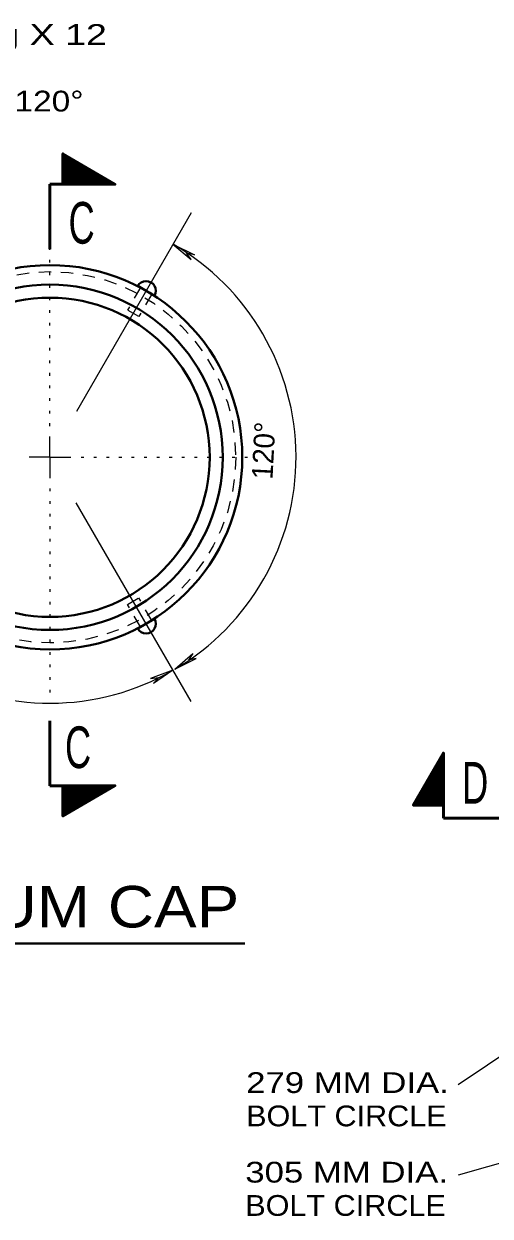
# Model space of a CAD drawing. Extents: x 312583 to 312854, y 144418 to 144597.
# Drawn here: x 312757.76 to 312774.81, y 144501.21 to 144544.83 of the extents above; entities that cross this region are included whole.
import ezdxf
from ezdxf.enums import TextEntityAlignment as Align

# ---------------------------------------------------------------- set-up
doc = ezdxf.new("R2010")
doc.units = 0
doc.header["$LTSCALE"] = 0.3
doc.linetypes.add('DOTTED', pattern=[1.5, 0.3, -1.2])
doc.linetypes.add('SHORT_DASHED', pattern=[2.7, 1.5, -1.2])
doc.layers.add('1', color=7, linetype='Continuous', lineweight=35)

msp = doc.modelspace()

# ---------------------------------------------------------------- linework, layer by layer
at = {"layer": '1'}
for p, q in [((312759.1879, 144540.0442), (312759.2032, 144540.0594)), ((312759.1879, 144539.9984), (312759.226, 144540.0442)), ((312759.1879, 144539.9374), (312759.2413, 144540.0289)), ((312759.1879, 144539.8917), (312759.2642, 144540.0137)), ((312759.1879, 144539.8459), (312759.287, 144540.0137)), ((312759.1879, 144539.8002), (312759.3023, 144539.9984)), ((312759.1879, 144539.7544), (312759.3252, 144539.9832)), ((312759.1879, 144539.7087), (312759.348, 144539.9679)), ((312759.1879, 144539.6629), (312759.3633, 144539.9679)), ((312759.1879, 144539.6172), (312759.3938, 144539.9527)), ((312759.1879, 144539.5562), (312759.409, 144539.9374)), ((312759.1879, 144539.5104), (312759.4319, 144539.9222)), ((312759.1879, 144539.4647), (312759.4548, 144539.9222)), ((312759.1879, 144539.4189), (312759.47, 144539.9069)), ((312759.1879, 144539.3732), (312759.4929, 144539.8917)), ((312759.1879, 144539.3274), (312759.5082, 144539.8764)), ((312759.1879, 144539.2664), (312759.531, 144539.8612)), ((312759.1879, 144539.2207), (312759.5539, 144539.8612)), ((312759.1879, 144539.1749), (312759.5692, 144539.8459)), ((312759.1879, 144539.1292), (312759.592, 144539.8307)), ((312759.1879, 144539.0834), (312759.6149, 144539.8154)), ((312759.1879, 144539.0377), (312759.6302, 144539.8002)), ((312759.1879, 144538.9919), (312759.6606, 144539.8002)), ((312759.2032, 144538.9614), (312759.6759, 144539.7849)), ((312759.2336, 144538.9614), (312759.6988, 144539.7697)), ((312759.2642, 144538.9614), (312759.7216, 144539.7544)), ((312759.287, 144538.9614), (312759.7369, 144539.7544)), ((312759.3175, 144538.9614), (312759.7598, 144539.7392)), ((312759.3404, 144538.9767), (312759.7826, 144539.7239)), ((312759.3709, 144538.9767), (312759.7979, 144539.7087)), ((312759.3938, 144538.9614), (312759.8208, 144539.7087)), ((312759.4243, 144538.9614), (312759.8436, 144539.6934)), ((312759.4548, 144538.9614), (312759.8589, 144539.6782)), ((312759.4776, 144538.9614), (312759.8818, 144539.6629)), ((312759.5082, 144538.9614), (312759.9046, 144539.6477)), ((312759.5386, 144538.9614), (312759.9275, 144539.6324)), ((312759.5615, 144538.9614), (312759.9428, 144539.6324)), ((312759.592, 144538.9767), (312759.9656, 144539.6172)), ((312759.6225, 144538.9614), (312759.9885, 144539.6019)), ((312759.6454, 144538.9614), (312760.0038, 144539.5867)), ((312759.6683, 144538.9614), (312760.0266, 144539.5867)), ((312759.6988, 144538.9614), (312760.0495, 144539.5714)), ((312759.7293, 144538.9614), (312760.0648, 144539.5562)), ((312759.7598, 144538.9614), (312760.0876, 144539.5409)), ((312759.7826, 144538.9614), (312760.1105, 144539.5409)), ((312759.8132, 144538.9614), (312760.1258, 144539.5257)), ((312759.836, 144538.9767), (312760.1563, 144539.5104)), ((312759.8665, 144538.9614), (312760.1715, 144539.4952)), ((312759.8894, 144538.9614), (312760.1944, 144539.4799)), ((312759.9199, 144538.9614), (312760.2173, 144539.4799)), ((312759.9504, 144538.9614), (312760.2325, 144539.4647)), ((312759.9733, 144538.9614), (312760.2554, 144539.4494)), ((312760.0038, 144538.9614), (312760.2783, 144539.4342)), ((312760.0343, 144538.9614), (312760.2935, 144539.4342)), ((312760.0572, 144538.9614), (312760.3164, 144539.4189)), ((312760.0876, 144538.9614), (312760.3393, 144539.4037)), ((312760.1182, 144538.9614), (312760.3545, 144539.3884)), ((312760.141, 144538.9614), (312760.3774, 144539.3884)), ((312760.1639, 144538.9614), (312760.4003, 144539.3732)), ((312760.1944, 144538.9614), (312760.4232, 144539.3579)), ((312760.2249, 144538.9614), (312760.4384, 144539.3427)), ((312760.2554, 144538.9614), (312760.4613, 144539.3274)), ((312760.2783, 144538.9614), (312760.4842, 144539.3274)), ((312760.3088, 144538.9614), (312760.4994, 144539.3122)), ((312760.3316, 144538.9614), (312760.5223, 144539.2969)), ((312760.3622, 144538.9614), (312760.5452, 144539.2817)), ((312760.385, 144538.9614), (312760.5604, 144539.2664)), ((312760.4155, 144538.9614), (312760.5833, 144539.2664)), ((312760.446, 144538.9614), (312760.6062, 144539.2512)), ((312760.4689, 144538.9614), (312760.6214, 144539.2359)), ((312760.4994, 144538.9614), (312760.6519, 144539.2207)), ((312760.5223, 144538.9614), (312760.6672, 144539.2207)), ((312760.5528, 144538.9614), (312760.69, 144539.2054)), ((312760.5833, 144538.9614), (312760.7129, 144539.1902)), ((312760.6062, 144538.9614), (312760.7282, 144539.1749)), ((312760.6366, 144538.9614), (312760.751, 144539.1749)), ((312760.6595, 144538.9614), (312760.7739, 144539.1597)), ((312760.69, 144538.9614), (312760.7892, 144539.1444)), ((312760.7205, 144538.9614), (312760.812, 144539.1292)), ((312760.751, 144538.9614), (312760.8349, 144539.1139)), ((312760.7739, 144538.9614), (312760.8502, 144539.0987)), ((312760.8044, 144538.9614), (312760.873, 144539.0987)), ((312760.8273, 144538.9614), (312760.8959, 144539.0834)), ((312760.8502, 144538.9614), (312760.9188, 144539.0682)), ((312760.8806, 144538.9614), (312760.934, 144539.0529)), ((312760.9112, 144538.9614), (312760.9569, 144539.0529)), ((312760.9416, 144538.9614), (312760.9798, 144539.0377)), ((312760.9645, 144538.9614), (312760.995, 144539.0224)), ((312760.995, 144538.9614), (312761.0179, 144539.0072)), ((312761.0179, 144538.9614), (312761.0408, 144539.0072)), ((312761.0484, 144538.9614), (312761.056, 144538.9919)), ((312761.0789, 144538.9614), (312761.0789, 144538.9767)), ((312773.105, 144517.8125), (312772.9525, 144517.8964)), ((312773.105, 144517.8354), (312772.9678, 144517.9116)), ((312773.105, 144517.8659), (312772.9754, 144517.9345)), ((312773.105, 144517.8888), (312772.9906, 144517.9574)), ((312773.105, 144517.9116), (312772.9982, 144517.9802)), ((312773.105, 144517.9421), (312773.0135, 144517.9955)), ((312773.105, 144517.9726), (312773.0211, 144518.0184)), ((312773.105, 144518.0031), (312773.0364, 144518.0412)), ((312773.105, 144518.026), (312773.044, 144518.0565)), ((312773.105, 144518.0565), (312773.0592, 144518.0794)), ((312773.105, 144518.0794), (312773.0669, 144518.1022)), ((312773.105, 144518.1099), (312773.0821, 144518.1175)), ((312773.105, 144518.1404), (312773.0898, 144518.1404)), ((312773.105, 144517.2254), (312772.7009, 144517.4618)), ((312773.105, 144517.2559), (312772.7085, 144517.4846)), ((312773.105, 144517.2864), (312772.7238, 144517.4999)), ((312773.105, 144517.3169), (312772.739, 144517.5228)), ((312773.105, 144517.3398), (312772.7466, 144517.5456)), ((312773.105, 144517.3702), (312772.7619, 144517.5609)), ((312773.105, 144517.3931), (312772.7771, 144517.5838)), ((312773.105, 144517.4236), (312772.7848, 144517.6066)), ((312773.105, 144517.4465), (312772.8, 144517.6219)), ((312773.105, 144517.477), (312772.8076, 144517.6448)), ((312773.105, 144517.5075), (312772.8229, 144517.6676)), ((312773.105, 144517.5304), (312772.8305, 144517.6829)), ((312773.105, 144517.5609), (312772.8458, 144517.7134)), ((312773.105, 144517.5838), (312772.8534, 144517.7286)), ((312773.105, 144517.6142), (312772.8686, 144517.7515)), ((312773.105, 144517.6448), (312772.8762, 144517.7744)), ((312773.105, 144517.6676), (312772.8915, 144517.7896)), ((312773.105, 144517.6981), (312772.8991, 144517.8125)), ((312773.105, 144517.721), (312772.9144, 144517.8354)), ((312773.105, 144517.7515), (312772.9296, 144517.8506)), ((312773.105, 144517.782), (312772.9372, 144517.8735)), ((312773.0974, 144516.6535), (312772.4569, 144517.0271)), ((312773.105, 144516.684), (312772.4645, 144517.05)), ((312773.105, 144516.7069), (312772.4798, 144517.0652)), ((312773.105, 144516.7298), (312772.4874, 144517.0881)), ((312773.105, 144516.7602), (312772.5026, 144517.111)), ((312773.105, 144516.7908), (312772.5102, 144517.1262)), ((312773.105, 144516.8212), (312772.5255, 144517.1491)), ((312773.105, 144516.8441), (312772.5331, 144517.172)), ((312773.105, 144516.8746), (312772.5484, 144517.1872)), ((312773.0974, 144516.8975), (312772.556, 144517.2178)), ((312773.105, 144516.928), (312772.5712, 144517.233)), ((312773.105, 144516.9509), (312772.5865, 144517.2559)), ((312773.105, 144516.9814), (312772.5941, 144517.2788)), ((312773.105, 144517.0119), (312772.6094, 144517.294)), ((312773.105, 144517.0348), (312772.617, 144517.3169)), ((312773.105, 144517.0652), (312772.6322, 144517.3398)), ((312773.105, 144517.0958), (312772.6399, 144517.355)), ((312773.105, 144517.1186), (312772.6551, 144517.3779)), ((312773.105, 144517.1491), (312772.6628, 144517.4008)), ((312773.105, 144517.1796), (312772.678, 144517.416)), ((312773.105, 144517.2025), (312772.6856, 144517.4389)), ((312759.1879, 144516.9328), (312759.6606, 144516.1246)), ((312759.1879, 144516.8794), (312759.6302, 144516.1169)), ((312759.1879, 144516.8413), (312759.6149, 144516.1017)), ((312759.1879, 144516.7879), (312759.592, 144516.094)), ((312759.1879, 144516.7422), (312759.5692, 144516.0788)), ((312759.1879, 144516.6964), (312759.5539, 144516.0636)), ((312759.1879, 144516.6507), (312759.531, 144516.0559)), ((312759.1879, 144516.5973), (312759.5082, 144516.0407)), ((312759.2032, 144516.9557), (312759.6759, 144516.1398)), ((312759.2336, 144516.9557), (312759.6988, 144516.1474)), ((312759.2642, 144516.9557), (312759.7216, 144516.1627)), ((312759.287, 144516.9557), (312759.7369, 144516.1703)), ((312759.3175, 144516.9557), (312759.7598, 144516.1856)), ((312759.3404, 144516.948), (312759.7826, 144516.1932)), ((312759.3709, 144516.948), (312759.7979, 144516.2084)), ((312759.3938, 144516.9557), (312759.8208, 144516.216)), ((312759.4243, 144516.9557), (312759.8436, 144516.2313)), ((312759.4548, 144516.9557), (312759.8589, 144516.2466)), ((312759.4776, 144516.9557), (312759.8818, 144516.2542)), ((312759.5082, 144516.9557), (312759.9046, 144516.2694)), ((312759.5386, 144516.9557), (312759.9275, 144516.2847)), ((312759.5615, 144516.9557), (312759.9428, 144516.2923)), ((312759.592, 144516.948), (312759.9656, 144516.3076)), ((312759.6225, 144516.9557), (312759.9885, 144516.3152)), ((312759.6454, 144516.9557), (312760.0038, 144516.3304)), ((312759.6683, 144516.9557), (312760.0266, 144516.338)), ((312759.6988, 144516.9557), (312760.0495, 144516.3533)), ((312759.7293, 144516.9557), (312760.0648, 144516.3609)), ((312759.7598, 144516.9557), (312760.0876, 144516.3762)), ((312759.7826, 144516.9557), (312760.1105, 144516.3838)), ((312759.8132, 144516.9557), (312760.1258, 144516.399)), ((312759.836, 144516.948), (312760.1563, 144516.4067)), ((312759.8665, 144516.9557), (312760.1715, 144516.4219)), ((312759.8894, 144516.9557), (312760.1944, 144516.4372)), ((312759.9199, 144516.9557), (312760.2173, 144516.4448)), ((312759.9504, 144516.9557), (312760.2325, 144516.46)), ((312759.9733, 144516.9557), (312760.2554, 144516.4677)), ((312760.0038, 144516.9557), (312760.2783, 144516.4829)), ((312760.0343, 144516.9557), (312760.2935, 144516.4906)), ((312760.0572, 144516.9557), (312760.3164, 144516.5058)), ((312760.0876, 144516.9557), (312760.3393, 144516.5134)), ((312760.1182, 144516.9557), (312760.3545, 144516.5287)), ((312760.141, 144516.9557), (312760.3774, 144516.5363)), ((312760.1639, 144516.9557), (312760.4003, 144516.5516)), ((312760.1944, 144516.9557), (312760.4232, 144516.5592)), ((312760.2249, 144516.9557), (312760.4384, 144516.5744)), ((312760.2554, 144516.9557), (312760.4613, 144516.5897)), ((312760.2783, 144516.9557), (312760.4842, 144516.5973)), ((312760.3088, 144516.9557), (312760.4994, 144516.6126)), ((312760.3316, 144516.9557), (312760.5223, 144516.6278)), ((312760.3622, 144516.9557), (312760.5452, 144516.6354)), ((312760.385, 144516.9557), (312760.5604, 144516.6507)), ((312760.4155, 144516.9557), (312760.5833, 144516.6583)), ((312760.446, 144516.9557), (312760.6062, 144516.6736)), ((312760.4689, 144516.9557), (312760.6214, 144516.6812)), ((312760.4994, 144516.9557), (312760.6519, 144516.6964)), ((312760.5223, 144516.9557), (312760.6672, 144516.704)), ((312760.5528, 144516.9557), (312760.69, 144516.7193)), ((312760.5833, 144516.9557), (312760.7129, 144516.7269)), ((312760.6062, 144516.9557), (312760.7282, 144516.7422)), ((312760.6366, 144516.9557), (312760.751, 144516.7498)), ((312760.6595, 144516.9557), (312760.7739, 144516.765)), ((312760.69, 144516.9557), (312760.7892, 144516.7803)), ((312760.7205, 144516.9557), (312760.812, 144516.7879)), ((312760.751, 144516.9557), (312760.8349, 144516.8032)), ((312760.7739, 144516.9557), (312760.8502, 144516.8184)), ((312760.8044, 144516.9557), (312760.873, 144516.826)), ((312760.8273, 144516.9557), (312760.8959, 144516.8413)), ((312760.8502, 144516.9557), (312760.9188, 144516.8489)), ((312760.8806, 144516.9557), (312760.934, 144516.8642)), ((312760.9112, 144516.9557), (312760.9569, 144516.8718)), ((312760.9416, 144516.9557), (312760.9798, 144516.887)), ((312760.9645, 144516.9557), (312760.995, 144516.8947)), ((312760.995, 144516.9557), (312761.0179, 144516.9099)), ((312761.0179, 144516.9557), (312761.0408, 144516.9176)), ((312761.0484, 144516.9557), (312761.056, 144516.9328)), ((312761.0789, 144516.9557), (312761.0789, 144516.9404)), ((312772.8, 144516.2494), (312772.2052, 144516.5925)), ((312772.8458, 144516.2494), (312772.2129, 144516.6154)), ((312772.8915, 144516.2494), (312772.2281, 144516.6306)), ((312772.9372, 144516.2494), (312772.2434, 144516.6535)), ((312772.9906, 144516.2494), (312772.251, 144516.6764)), ((312773.0288, 144516.2494), (312772.2662, 144516.6916)), ((312773.0821, 144516.2494), (312772.2739, 144516.7221)), ((312773.105, 144516.2646), (312772.2891, 144516.7374)), ((312773.105, 144516.2951), (312772.2968, 144516.7602)), ((312773.105, 144516.3256), (312772.312, 144516.7831)), ((312773.105, 144516.3485), (312772.3196, 144516.7984)), ((312773.105, 144516.379), (312772.3349, 144516.8212)), ((312773.0974, 144516.4019), (312772.3425, 144516.8441)), ((312773.0974, 144516.4324), (312772.3578, 144516.8594)), ((312773.105, 144516.4552), (312772.3654, 144516.8822)), ((312773.105, 144516.4858), (312772.3806, 144516.9051)), ((312773.105, 144516.5162), (312772.3959, 144516.9204)), ((312773.105, 144516.5391), (312772.4035, 144516.9432)), ((312773.105, 144516.5696), (312772.4188, 144516.9661)), ((312773.105, 144516.6001), (312772.434, 144516.989)), ((312773.105, 144516.623), (312772.4416, 144517.0042)), ((312759.1879, 144516.5516), (312759.4929, 144516.0254)), ((312759.1879, 144516.5058), (312759.47, 144516.0178)), ((312759.1879, 144516.4524), (312759.4548, 144516.0026)), ((312759.1879, 144516.4067), (312759.4319, 144515.9949)), ((312759.1879, 144516.3609), (312759.409, 144515.9797)), ((312759.1879, 144516.3076), (312759.3938, 144515.972)), ((312759.1879, 144516.2618), (312759.3633, 144515.9568)), ((312759.1879, 144516.216), (312759.348, 144515.9492)), ((312759.1879, 144516.1703), (312759.3252, 144515.9339)), ((312772.0299, 144516.2494), (312772.0146, 144516.2646)), ((312772.0756, 144516.2494), (312772.0222, 144516.2875)), ((312772.129, 144516.2494), (312772.0375, 144516.3028)), ((312772.1748, 144516.2494), (312772.0528, 144516.3256)), ((312772.2281, 144516.2494), (312772.0604, 144516.3485)), ((312772.2662, 144516.2494), (312772.0756, 144516.3638)), ((312772.3196, 144516.2494), (312772.0832, 144516.3866)), ((312772.3654, 144516.2494), (312772.0985, 144516.4095)), ((312772.4111, 144516.2494), (312772.1061, 144516.4248)), ((312772.4569, 144516.2494), (312772.1214, 144516.4552)), ((312772.5102, 144516.2494), (312772.129, 144516.4705)), ((312772.556, 144516.2494), (312772.1442, 144516.4934)), ((312772.6018, 144516.2494), (312772.1519, 144516.5162)), ((312772.6551, 144516.2494), (312772.1671, 144516.5315)), ((312772.7009, 144516.2494), (312772.1748, 144516.5544)), ((312772.7466, 144516.2494), (312772.19, 144516.5696)), ((312759.1879, 144516.1169), (312759.3023, 144515.9263)), ((312759.1879, 144516.0788), (312759.287, 144515.911)), ((312759.1879, 144516.0254), (312759.2642, 144515.9034)), ((312759.1879, 144515.9797), (312759.2413, 144515.8882)), ((312759.1879, 144515.9263), (312759.226, 144515.8729)), ((312759.1879, 144515.8806), (312759.2032, 144515.8653))]:
    msp.add_line(p, q, dxfattribs=at)
at = {"layer": '1', "lineweight": 53}
for p, q in [((312758.7152, 144536.5824), (312758.7152, 144538.9614)), ((312759.1879, 144538.9614), (312758.7152, 144538.9614)), ((312758.7152, 144519.3347), (312758.7152, 144516.9557)), ((312759.1879, 144516.9557), (312758.7152, 144516.9557)), ((312773.105, 144516.2494), (312773.105, 144515.7766)), ((312775.484, 144515.7766), (312773.105, 144515.7766))]:
    msp.add_line(p, q, dxfattribs=at)
at = {"layer": '1', "linetype": 'DOTTED', "lineweight": 13}
for p, q in [((312758.7152, 144530.1164), (312758.7152, 144537.7414)), ((312759.8589, 144528.9727), (312766.058, 144528.9727)), ((312758.7152, 144527.8289), (312758.7152, 144520.3259))]:
    msp.add_line(p, q, dxfattribs=at)
at = {"layer": '1', "lineweight": 13}
for p, q in [((312763.8773, 144537.9092), (312759.6835, 144530.6426)), ((312763.2139, 144536.7654), (312763.8849, 144536.2088)), ((312763.2139, 144536.7654), (312763.9993, 144536.3842)), ((312763.8849, 144536.2088), (312763.7095, 144536.4452)), ((312763.9993, 144536.3842), (312763.7095, 144536.4452)), ((312758.7152, 144528.9727), (312758.7152, 144529.7352)), ((312758.7152, 144528.9727), (312757.9526, 144528.9727)), ((312758.7152, 144528.9727), (312758.7152, 144528.2102)), ((312758.7152, 144528.9727), (312759.4776, 144528.9727)), ((312763.8773, 144520.0362), (312759.6759, 144527.3028)), ((312763.2825, 144521.2257), (312763.9459, 144521.7899)), ((312763.2825, 144521.2257), (312764.0603, 144521.6069)), ((312763.9459, 144521.7899), (312763.7782, 144521.5459)), ((312764.0603, 144521.6069), (312763.7782, 144521.5459)), ((312763.2139, 144521.1799), (312762.398, 144520.8826)), ((312763.2139, 144521.1799), (312762.4972, 144520.6919)), ((312762.398, 144520.8826), (312762.6954, 144520.913)), ((312762.4972, 144520.6919), (312762.6954, 144520.913)), ((312788.233, 144515.7766), (312773.6388, 144506.0166)), ((312780.5318, 144504.6975), (312773.6388, 144502.7074))]:
    msp.add_line(p, q, dxfattribs=at)
at = {"layer": '1', "linetype": 'SHORT_DASHED', "lineweight": 25}
for p, q in [((312762.0244, 144535.1794), (312761.5516, 144534.3559)), ((312762.4362, 144534.943), (312761.9634, 144534.1196)), ((312761.9634, 144534.1196), (312761.5516, 144534.3559)), ((312761.5516, 144523.5894), (312761.9634, 144523.8334)), ((312762.0244, 144522.7659), (312761.5516, 144523.5894)), ((312762.4362, 144523.0023), (312761.9634, 144523.8334))]:
    msp.add_line(p, q, dxfattribs=at)
at = {"layer": '1', "lineweight": 40}
for p, q in [((312761.9253, 144535.2404), (312762.5429, 144534.882)), ((312762.5429, 144523.0633), (312761.9253, 144522.7049)), ((312740.768, 144511.1801), (312765.8427, 144511.1801))]:
    msp.add_line(p, q, dxfattribs=at)
at = {"layer": '1', "lineweight": 53}
for points in [[(312759.1879, 144538.9614), (312759.1879, 144540.0747), (312761.0942, 144538.9614)], [(312773.105, 144516.2494), (312771.9994, 144516.2494), (312773.105, 144518.1556)], [(312759.1879, 144516.9557), (312759.1879, 144515.85), (312761.0942, 144516.9557)]]:
    msp.add_lwpolyline(points, close=True, dxfattribs=at)
at = {"layer": '1', "lineweight": 40}
for radius in [7.0302, 6.3154, 5.8388]:
    msp.add_circle((312758.7171, 144528.9727), radius, dxfattribs=at)
at = {"layer": '1', "linetype": 'SHORT_DASHED', "lineweight": 25}
msp.add_circle((312758.7171, 144528.9727), 6.792, dxfattribs=at)
at = {"layer": '1', "lineweight": 13}
for start, end in [(300.50993, 59.99393), (180.50993, 299.99393)]:
    msp.add_arc((312758.7171, 144528.9727), 8.996, start, end, dxfattribs=at)
at = {"layer": '1', "lineweight": 40}
for centre, start, end in [((312762.2328, 144535.0641), 329.52448, 150.47552), ((312762.2345, 144522.8822), 209.52448, 30.47552)]:
    msp.add_arc(centre, 0.3555, start, end, dxfattribs=at)

# ---------------------------------------------------------------- texts
at = {"layer": '1'}
for s, width, p in [('DRILL & TAP FOR M5 X 0.8-6g X 12', 1.35, (312738.2268, 144544.0574)), ('FURNISH 3 PER UNIT. SPACE @ 120°', 1.2, (312738.2268, 144541.6224)), ('279 MM DIA.', 1.25, (312765.8895, 144505.7166)), ('BOLT CIRCLE', 1.1, (312765.8895, 144504.4991)), ('305 MM DIA.', 1.25, (312765.8579, 144502.4403)), ('BOLT CIRCLE', 1.1, (312765.8579, 144501.2228))]:
    msp.add_text(s, height=0.76, dxfattribs=dict(at, width=width)).set_placement(p)
for s, height, width, p in [('C', 1.523, 0.65, (312759.8741, 144536.7883)), ('C', 1.523, 0.65, (312759.7446, 144517.6038)), ('D', 1.525, 0.65, (312774.2639, 144516.3028)), ('CAST ALUMINUM CAP', 1.52, 1.15, (312753.2355, 144511.7726))]:
    msp.add_text(s, height=height, dxfattribs=dict(at, width=width)).set_placement(p, align=Align.CENTER)
msp.add_text('120°', height=0.76, rotation=87, dxfattribs=at).set_placement((312766.9067, 144529.1948), align=Align.CENTER)

doc.saveas('drawing.dxf')
